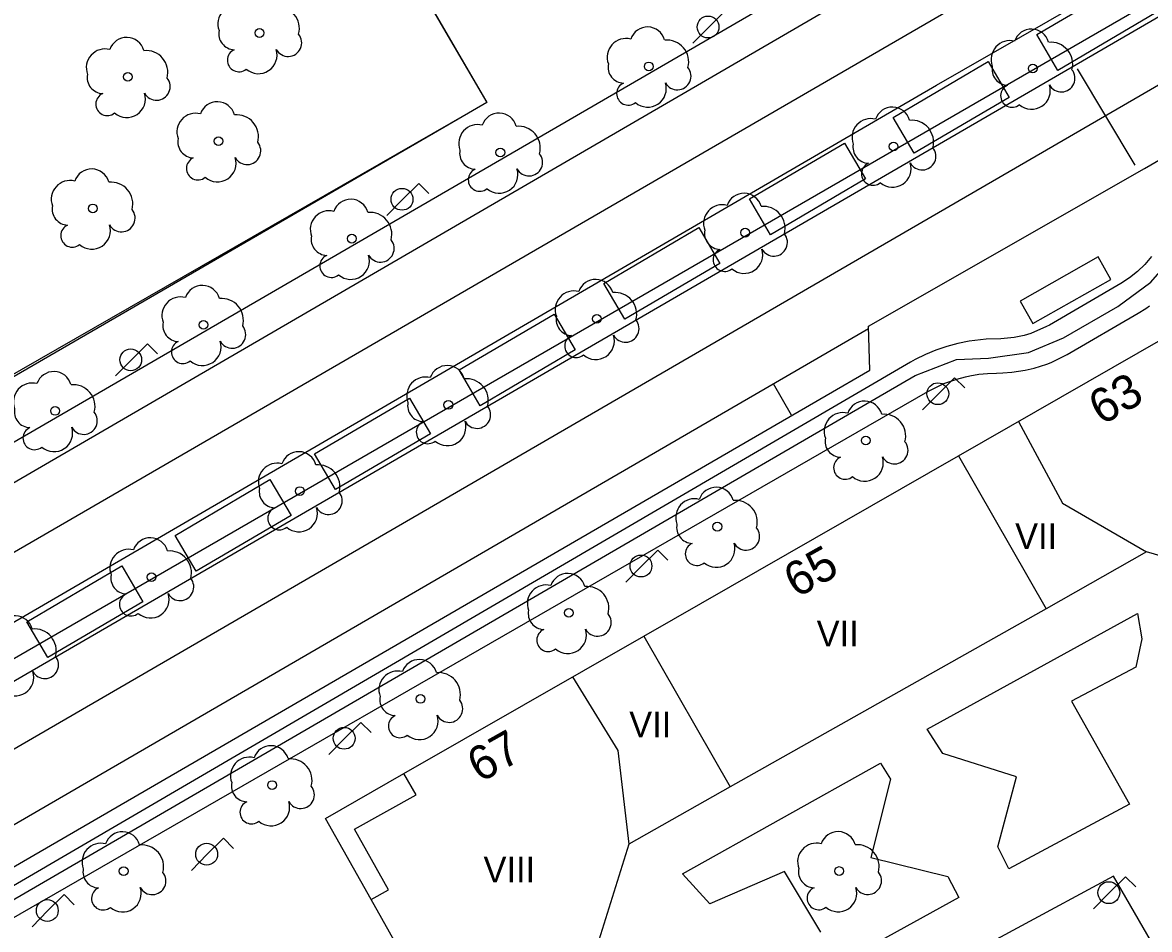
# Model space of a CAD drawing. Extents: x 282771 to 285132, y 4823109 to 4825496.
# Drawn here: x 283766.5 to 283832.3, y 4823743.4 to 4823796.3 of the extents above; entities that cross this region are included whole.
import ezdxf

# ---------------------------------------------------------------- set-up
doc = ezdxf.new("R2010")
doc.units = 0
for name, color, linetype in [('ACERA-BORDILLO', 7, 'Continuous'), ('ACERA-INTERIOR', 7, 'Continuous'), ('APARCAMIENTO', 7, 'Continuous'), ('ARBOL', 7, 'Continuous'), ('BORDILLO', 7, 'Continuous'), ('CALLE-EJE', 7, 'Continuous'), ('CARRIL-BICI-AREA', 7, 'Continuous'), ('CARRIL-BICI-EJE', 7, 'Continuous'), ('EDIFICIO', 7, 'Continuous'), ('FAROLA', 7, 'Continuous'), ('MARQUESINA-BUS', 7, 'Continuous'), ('MEDIANERA', 7, 'Continuous'), ('NUM-PORTAL', 7, 'Continuous'), ('PARQUE-JARDIN-AREA', 7, 'Continuous'), ('SENAL-VIARIA', 7, 'Continuous'), ('TXT-ALTURA-EDIFICIO', 7, 'Continuous'), ('ZONA-VERDE', 7, 'Continuous')]:
    doc.layers.add(name, color=color, linetype=linetype)

msp = doc.modelspace()

# ---------------------------------------------------------------- linework, layer by layer
at = {"layer": 'ACERA-BORDILLO'}
for points in [[(283686.965, 4823723.606), (283698.624, 4823730.373), (283698.444, 4823732.697), (283821.968, 4823804.368)], [(283708.328, 4823713.648), (283815.96, 4823776.062), (283815.877, 4823778.645), (283831.988, 4823787.83), (283834.54, 4823789.311)]]:
    msp.add_lwpolyline(points, dxfattribs=at)
at = {"layer": 'ACERA-INTERIOR'}
for points in [[(283786.872, 4823745.187), (283784.202, 4823749.927), (283788.772, 4823752.547)], [(283844.381, 4823721.987), (283830.181, 4823746.557), (283807.691, 4823734.427), (283822.111, 4823709.407), (283844.381, 4823721.987)]]:
    msp.add_lwpolyline(points, dxfattribs=at)
at = {"layer": 'APARCAMIENTO'}
for points in [[(283822.998, 4823802.633), (283760.545, 4823766.338), (283759.489, 4823768.01)], [(283811.392, 4823773.448), (283810.336, 4823775.267)]]:
    msp.add_lwpolyline(points, dxfattribs=at)
at = {"layer": 'ARBOL'}
for centre in [(283780.343, 4823795.741), (283803.06, 4823793.793), (283825.466, 4823793.668), (283772.668, 4823793.183), (283777.955, 4823789.431), (283794.399, 4823788.768), (283817.349, 4823789.118), (283770.622, 4823785.509), (283808.688, 4823784.093), (283785.739, 4823783.743), (283800.028, 4823779.068), (283777.078, 4823778.718), (283768.417, 4823773.693), (283791.367, 4823774.043), (283815.723, 4823771.968), (283782.706, 4823769.018), (283807.063, 4823766.943), (283774.046, 4823763.993), (283798.402, 4823761.918), (283789.741, 4823756.893), (283781.081, 4823751.868), (283772.42, 4823746.843), (283814.175, 4823746.853)]:
    msp.add_circle(centre, 0.255, dxfattribs=at)
for centre, radius, start, end in [((283779.013, 4823796.271), 1.097, 75.4318, 200.55608), ((283781.403, 4823796.001), 1.272, 345.03273, 95.79925), ((283778.903, 4823795.701), 0.935, 168.59898, 268.13236), ((283782.013, 4823795.171), 0.797, 208.96246, 38.99103), ((283802.99, 4823795.053), 1.038, 15.64228, 161.38435), ((283825.396, 4823794.928), 1.038, 15.64228, 161.38435), ((283772.598, 4823794.443), 1.038, 15.64228, 161.38435), ((283801.73, 4823794.323), 1.097, 75.4318, 200.55608), ((283804.12, 4823794.053), 1.272, 345.03273, 95.79925), ((283824.136, 4823794.198), 1.097, 75.4318, 200.55608), ((283826.526, 4823793.928), 1.272, 345.03273, 95.79925), ((283771.338, 4823793.713), 1.097, 75.4318, 200.55608), ((283773.728, 4823793.443), 1.272, 345.03273, 95.79925), ((283779.143, 4823794.151), 0.672, 113.73672, 309.4725), ((283780.283, 4823794.451), 1.086, 228.95447, 17.92796), ((283801.62, 4823793.753), 0.935, 168.59898, 268.13236), ((283804.73, 4823793.223), 0.797, 208.96246, 38.99103), ((283824.026, 4823793.628), 0.935, 168.59898, 268.13236), ((283827.136, 4823793.098), 0.797, 208.96246, 38.99103), ((283771.228, 4823793.143), 0.935, 168.59898, 268.13236), ((283774.338, 4823792.613), 0.797, 208.96246, 38.99103), ((283772.608, 4823791.893), 1.086, 228.95447, 17.92796), ((283801.86, 4823792.203), 0.672, 113.73672, 309.4725), ((283803, 4823792.503), 1.086, 228.95447, 17.92796), ((283824.266, 4823792.078), 0.672, 113.73672, 309.4725), ((283825.406, 4823792.378), 1.086, 228.95447, 17.92796), ((283771.468, 4823791.593), 0.672, 113.73672, 309.4725), ((283777.885, 4823790.691), 1.038, 15.64228, 161.38435), ((283776.625, 4823789.961), 1.097, 75.4318, 200.55608), ((283779.015, 4823789.691), 1.272, 345.03273, 95.79925), ((283794.329, 4823790.028), 1.038, 15.64228, 161.38435), ((283817.279, 4823790.378), 1.038, 15.64228, 161.38435), ((283793.07, 4823789.298), 1.097, 75.4318, 200.55608), ((283795.459, 4823789.028), 1.272, 345.03273, 95.79925), ((283816.019, 4823789.648), 1.097, 75.4318, 200.55608), ((283818.409, 4823789.378), 1.272, 345.03273, 95.79925), ((283776.515, 4823789.391), 0.935, 168.59898, 268.13236), ((283779.625, 4823788.861), 0.797, 208.96246, 38.99103), ((283815.909, 4823789.078), 0.935, 168.59898, 268.13236), ((283819.019, 4823788.548), 0.797, 208.96246, 38.99103), ((283776.755, 4823787.841), 0.672, 113.73672, 309.4725), ((283777.895, 4823788.141), 1.086, 228.95447, 17.92796), ((283792.96, 4823788.728), 0.935, 168.59898, 268.13236), ((283796.069, 4823788.198), 0.797, 208.96246, 38.99103), ((283770.552, 4823786.769), 1.038, 15.64228, 161.38435), ((283793.2, 4823787.178), 0.672, 113.73672, 309.4725), ((283794.339, 4823787.478), 1.086, 228.95447, 17.92796), ((283816.149, 4823787.528), 0.672, 113.73672, 309.4725), ((283817.289, 4823787.828), 1.086, 228.95447, 17.92796), ((283769.292, 4823786.039), 1.097, 75.4318, 200.55608), ((283771.682, 4823785.769), 1.272, 345.03273, 95.79925), ((283808.618, 4823785.353), 1.038, 15.64228, 161.38435), ((283769.182, 4823785.469), 0.935, 168.59898, 268.13236), ((283785.669, 4823785.003), 1.038, 15.64228, 161.38435), ((283807.358, 4823784.623), 1.097, 75.4318, 200.55608), ((283772.292, 4823784.939), 0.797, 208.96246, 38.99103), ((283784.409, 4823784.273), 1.097, 75.4318, 200.55608), ((283786.799, 4823784.003), 1.272, 345.03273, 95.79925), ((283809.748, 4823784.353), 1.272, 345.03273, 95.79925), ((283769.422, 4823783.919), 0.672, 113.73672, 309.4725), ((283770.562, 4823784.219), 1.086, 228.95447, 17.92796), ((283784.299, 4823783.703), 0.935, 168.59898, 268.13236), ((283807.248, 4823784.053), 0.935, 168.59898, 268.13236), ((283810.358, 4823783.523), 0.797, 208.96246, 38.99103), ((283787.409, 4823783.173), 0.797, 208.96246, 38.99103), ((283807.488, 4823782.503), 0.672, 113.73672, 309.4725), ((283808.628, 4823782.803), 1.086, 228.95447, 17.92796), ((283784.539, 4823782.153), 0.672, 113.73672, 309.4725), ((283785.679, 4823782.453), 1.086, 228.95447, 17.92796), ((283799.958, 4823780.328), 1.038, 15.64228, 161.38435), ((283777.008, 4823779.978), 1.038, 15.64228, 161.38435), ((283798.698, 4823779.598), 1.097, 75.4318, 200.55608), ((283801.088, 4823779.328), 1.272, 345.03273, 95.79925), ((283775.748, 4823779.248), 1.097, 75.4318, 200.55608), ((283778.138, 4823778.978), 1.272, 345.03273, 95.79925), ((283798.588, 4823779.028), 0.935, 168.59898, 268.13236), ((283775.638, 4823778.678), 0.935, 168.59898, 268.13236), ((283778.748, 4823778.148), 0.797, 208.96246, 38.99103), ((283801.698, 4823778.498), 0.797, 208.96246, 38.99103), ((283777.018, 4823777.428), 1.086, 228.95447, 17.92796), ((283798.828, 4823777.478), 0.672, 113.73672, 309.4725), ((283799.968, 4823777.778), 1.086, 228.95447, 17.92796), ((283775.878, 4823777.128), 0.672, 113.73672, 309.4725), ((283768.347, 4823774.953), 1.038, 15.64228, 161.38435), ((283791.297, 4823775.303), 1.038, 15.64228, 161.38435), ((283767.087, 4823774.223), 1.097, 75.4318, 200.55608), ((283769.477, 4823773.953), 1.272, 345.03273, 95.79925), ((283790.037, 4823774.573), 1.097, 75.4318, 200.55608), ((283792.427, 4823774.303), 1.272, 345.03273, 95.79925), ((283766.977, 4823773.653), 0.935, 168.59898, 268.13236), ((283789.927, 4823774.003), 0.935, 168.59898, 268.13236), ((283793.037, 4823773.473), 0.797, 208.96246, 38.99103), ((283815.653, 4823773.228), 1.038, 15.64228, 161.38435), ((283770.087, 4823773.123), 0.797, 208.96246, 38.99103), ((283814.393, 4823772.498), 1.097, 75.4318, 200.55608), ((283816.783, 4823772.228), 1.272, 345.03273, 95.79925), ((283767.217, 4823772.103), 0.672, 113.73672, 309.4725), ((283768.357, 4823772.403), 1.086, 228.95447, 17.92796), ((283790.167, 4823772.453), 0.672, 113.73672, 309.4725), ((283791.307, 4823772.753), 1.086, 228.95447, 17.92796), ((283814.283, 4823771.928), 0.935, 168.59898, 268.13236), ((283817.393, 4823771.398), 0.797, 208.96246, 38.99103), ((283782.636, 4823770.278), 1.038, 15.64228, 161.38435), ((283781.376, 4823769.548), 1.097, 75.4318, 200.55608), ((283783.766, 4823769.278), 1.272, 345.03273, 95.79925), ((283814.523, 4823770.378), 0.672, 113.73672, 309.4725), ((283815.663, 4823770.678), 1.086, 228.95447, 17.92796), ((283806.993, 4823768.203), 1.038, 15.64228, 161.38435), ((283781.266, 4823768.978), 0.935, 168.59898, 268.13236), ((283784.376, 4823768.448), 0.797, 208.96246, 38.99103), ((283805.733, 4823767.473), 1.097, 75.4318, 200.55608), ((283781.506, 4823767.428), 0.672, 113.73672, 309.4725), ((283782.646, 4823767.728), 1.086, 228.95447, 17.92796), ((283808.123, 4823767.203), 1.272, 345.03273, 95.79925), ((283805.623, 4823766.903), 0.935, 168.59898, 268.13236), ((283808.733, 4823766.373), 0.797, 208.96246, 38.99103), ((283773.976, 4823765.253), 1.038, 15.64228, 161.38435), ((283805.863, 4823765.353), 0.672, 113.73672, 309.4725), ((283807.003, 4823765.653), 1.086, 228.95447, 17.92796), ((283772.716, 4823764.523), 1.097, 75.4318, 200.55608), ((283775.106, 4823764.253), 1.272, 345.03273, 95.79925), ((283772.606, 4823763.953), 0.935, 168.59898, 268.13236), ((283798.332, 4823763.178), 1.038, 15.64228, 161.38435), ((283775.716, 4823763.423), 0.797, 208.96246, 38.99103), ((283797.072, 4823762.448), 1.097, 75.4318, 200.55608), ((283799.462, 4823762.178), 1.272, 345.03273, 95.79925), ((283772.846, 4823762.403), 0.672, 113.73672, 309.4725), ((283773.986, 4823762.703), 1.086, 228.95447, 17.92796), ((283796.962, 4823761.878), 0.935, 168.59898, 268.13236), ((283766.083, 4823760.705), 1.038, 15.64228, 161.38435), ((283800.072, 4823761.348), 0.797, 208.96246, 38.99103), ((283767.213, 4823759.705), 1.272, 345.03273, 95.79925), ((283797.202, 4823760.328), 0.672, 113.73672, 309.4725), ((283798.342, 4823760.628), 1.086, 228.95447, 17.92796), ((283767.823, 4823758.875), 0.797, 208.96246, 38.99103), ((283789.671, 4823758.153), 1.038, 15.64228, 161.38435), ((283766.093, 4823758.155), 1.086, 228.95447, 17.92796), ((283788.411, 4823757.423), 1.097, 75.4318, 200.55608), ((283790.801, 4823757.153), 1.272, 345.03273, 95.79925), ((283788.301, 4823756.853), 0.935, 168.59898, 268.13236), ((283791.411, 4823756.323), 0.797, 208.96246, 38.99103), ((283788.541, 4823755.303), 0.672, 113.73672, 309.4725), ((283789.681, 4823755.603), 1.086, 228.95447, 17.92796), ((283781.011, 4823753.128), 1.038, 15.64228, 161.38435), ((283779.751, 4823752.398), 1.097, 75.4318, 200.55608), ((283782.141, 4823752.128), 1.272, 345.03273, 95.79925), ((283779.641, 4823751.828), 0.935, 168.59898, 268.13236), ((283782.751, 4823751.298), 0.797, 208.96246, 38.99103), ((283779.881, 4823750.278), 0.672, 113.73672, 309.4725), ((283781.021, 4823750.578), 1.086, 228.95447, 17.92796), ((283772.35, 4823748.103), 1.038, 15.64228, 161.38435), ((283814.105, 4823748.113), 1.038, 15.64228, 161.38435), ((283771.09, 4823747.373), 1.097, 75.4318, 200.55608), ((283773.48, 4823747.103), 1.272, 345.03273, 95.79925), ((283812.845, 4823747.383), 1.097, 75.4318, 200.55608), ((283815.235, 4823747.113), 1.272, 345.03273, 95.79925), ((283770.98, 4823746.803), 0.935, 168.59898, 268.13236), ((283812.735, 4823746.813), 0.935, 168.59898, 268.13236), ((283774.09, 4823746.273), 0.797, 208.96246, 38.99103), ((283815.845, 4823746.283), 0.797, 208.96246, 38.99103), ((283771.22, 4823745.253), 0.672, 113.73672, 309.4725), ((283772.36, 4823745.553), 1.086, 228.95447, 17.92796), ((283812.975, 4823745.263), 0.672, 113.73672, 309.4725), ((283814.115, 4823745.563), 1.086, 228.95447, 17.92796)]:
    msp.add_arc(centre, radius, start, end, dxfattribs=at)
at = {"layer": 'BORDILLO'}
for points in [[(283691.749, 4823718.19), (283819.843, 4823792.692), (283831.283, 4823799.266)], [(283834.164, 4823797.465), (283693.206, 4823715.678), (283692.966, 4823715.567), (283692.693, 4823715.498), (283692.4, 4823715.484), (283692.105, 4823715.531), (283691.825, 4823715.637), (283691.578, 4823715.794), (283691.375, 4823715.989), (283691.222, 4823716.205), (283691.11, 4823716.446), (283691.042, 4823716.719), (283691.028, 4823717.011), (283691.075, 4823717.307), (283691.181, 4823717.586), (283691.338, 4823717.834), (283691.533, 4823718.036), (283691.749, 4823718.19)]]:
    msp.add_lwpolyline(points, dxfattribs=at)
at = {"layer": 'CALLE-EJE'}
msp.add_lwpolyline([(283685.293, 4823712.647), (283840.771, 4823802.436)], dxfattribs=at)
at = {"layer": 'CARRIL-BICI-AREA'}
for points in [[(283832.393, 4823782.701), (283832.006, 4823782.243), (283831.579, 4823781.821), (283831.11, 4823781.45), (283830.613, 4823781.124), (283826.444, 4823778.705), (283826.27, 4823778.611), (283825.359, 4823778.212), (283824.976, 4823778.096), (283824.388, 4823777.974), (283823.597, 4823777.899), (283822.741, 4823777.875), (283822.411, 4823777.844), (283821.752, 4823777.759), (283821.098, 4823777.631), (283820.453, 4823777.459), (283819.822, 4823777.245), (283819.208, 4823776.99), (283818.616, 4823776.697), (283818.326, 4823776.541), (283706.898, 4823711.519)], [(283687.107, 4823698.758), (283819.354, 4823774.823), (283819.812, 4823775.069), (283820.289, 4823775.286), (283821.032, 4823775.55), (283821.541, 4823775.687), (283821.797, 4823775.748), (283822.316, 4823775.834), (283822.837, 4823775.886), (283823.357, 4823775.905), (283823.73, 4823775.914), (283824.251, 4823775.949), (283825.03, 4823776.062), (283825.543, 4823776.182), (283826.293, 4823776.43), (283826.538, 4823776.523), (283827.244, 4823776.863), (283827.473, 4823776.987), (283831.626, 4823779.397), (283832.068, 4823779.672), (283832.28, 4823779.825)]]:
    msp.add_lwpolyline(points, dxfattribs=at)
at = {"layer": 'CARRIL-BICI-EJE'}
msp.add_lwpolyline([(283510.08, 4823597.633), (283706.223, 4823710.47), (283818.613, 4823775.756), (283821.019, 4823776.694), (283822.894, 4823776.775), (283825.218, 4823777.102), (283827.257, 4823777.958), (283830.437, 4823779.794), (283832.354, 4823781.206), (283833.565, 4823782.581), (283834.753, 4823784.562), (283836.081, 4823785.728), (283840.159, 4823788.035), (283860.751, 4823800.066)], dxfattribs=at)
at = {"layer": 'EDIFICIO'}
for points in [[(283786.872, 4823745.187), (283787.872, 4823745.747), (283785.882, 4823749.287), (283789.482, 4823751.307), (283788.772, 4823752.547), (283802.781, 4823760.557), (283821.141, 4823771.077), (283834.681, 4823778.837), (283835.391, 4823777.577), (283839.011, 4823779.617), (283841.031, 4823776.017), (283842.321, 4823776.737), (283850.911, 4823761.347), (283861.741, 4823741.987), (283869.831, 4823727.557)], [(283870.931, 4823723.667), (283867.291, 4823721.627), (283868.011, 4823720.337), (283852.961, 4823711.937), (283848.093, 4823720.613), (283855.141, 4823724.567), (283856.781, 4823730.677), (283853.091, 4823737.147), (283842.131, 4823756.437), (283837.971, 4823763.767), (283832.111, 4823765.467), (283826.251, 4823762.157), (283807.821, 4823751.767), (283801.901, 4823748.427), (283799.961, 4823742.197), (283804.031, 4823735.347), (283795.332, 4823730.127), (283786.872, 4823745.187)]]:
    msp.add_lwpolyline(points, dxfattribs=at)
at = {"layer": 'FAROLA'}
for p, q in [((283807.503, 4823797.019), (283806.563, 4823796.089)), ((283806.563, 4823796.089), (283805.633, 4823795.149)), ((283789.643, 4823786.969), (283788.703, 4823786.039)), ((283790.233, 4823786.379), (283789.643, 4823786.969)), ((283788.703, 4823786.039), (283787.773, 4823785.099)), ((283773.813, 4823777.606), (283772.873, 4823776.676)), ((283774.403, 4823777.016), (283773.813, 4823777.606)), ((283772.873, 4823776.676), (283771.943, 4823775.736)), ((283820.908, 4823775.627), (283819.968, 4823774.697)), ((283821.498, 4823775.037), (283820.908, 4823775.627)), ((283819.968, 4823774.697), (283819.038, 4823773.757)), ((283803.587, 4823765.577), (283802.647, 4823764.647)), ((283804.177, 4823764.987), (283803.587, 4823765.577)), ((283802.647, 4823764.647), (283801.717, 4823763.707)), ((283786.265, 4823755.527), (283785.325, 4823754.597)), ((283786.855, 4823754.937), (283786.265, 4823755.527)), ((283785.325, 4823754.597), (283784.395, 4823753.657)), ((283778.243, 4823748.763), (283777.303, 4823747.833)), ((283778.833, 4823748.173), (283778.243, 4823748.763)), ((283777.303, 4823747.833), (283776.373, 4823746.893)), ((283830.887, 4823746.522), (283829.947, 4823745.592)), ((283831.477, 4823745.932), (283830.887, 4823746.522)), ((283829.947, 4823745.592), (283829.017, 4823744.652)), ((283768.944, 4823745.477), (283768.004, 4823744.547)), ((283769.534, 4823744.887), (283768.944, 4823745.477)), ((283768.004, 4823744.547), (283767.074, 4823743.607))]:
    msp.add_line(p, q, dxfattribs=at)
for centre in [(283806.523, 4823796.089), (283788.663, 4823786.039), (283772.833, 4823776.676), (283819.928, 4823774.697), (283802.607, 4823764.647), (283785.285, 4823754.597), (283777.263, 4823747.833), (283829.907, 4823745.592), (283767.964, 4823744.547)]:
    msp.add_circle(centre, 0.637, dxfattribs=at)
at = {"layer": 'MARQUESINA-BUS'}
msp.add_lwpolyline([(283825.481, 4823778.795), (283830.025, 4823781.366), (283829.286, 4823782.673), (283824.742, 4823780.102), (283825.481, 4823778.795)], dxfattribs=at)
at = {"layer": 'MEDIANERA'}
for points in [[(283824.631, 4823773.077), (283827.211, 4823768.307), (283832.111, 4823765.467)], [(283821.141, 4823771.077), (283826.251, 4823762.157)], [(283802.781, 4823760.557), (283807.821, 4823751.767)], [(283798.611, 4823758.177), (283801.261, 4823753.877), (283801.901, 4823748.427)]]:
    msp.add_lwpolyline(points, dxfattribs=at)
at = {"layer": 'PARQUE-JARDIN-AREA'}
msp.add_lwpolyline([(283728.041, 4823827.883), (283730.641, 4823830.661), (283732.016, 4823831.84), (283745.833, 4823816.067), (283838.477, 4823896.142), (283853.871, 4823877.753), (283821.415, 4823849.784), (283818.024, 4823845.784), (283817.33, 4823844.721), (283816.785, 4823843.548), (283816.303, 4823842.103), (283815.882, 4823840.206), (283815.542, 4823838.304), (283810.304, 4823834.874), (283778.974, 4823816.824), (283793.604, 4823791.683), (283763.272, 4823774.291), (283760.222, 4823772.248)], close=True, dxfattribs=at)
at = {"layer": 'SENAL-VIARIA'}
msp.add_line((283815.882, 4823778.485), (283707.273, 4823715.467), dxfattribs=at)
for points in [[(283830.653, 4823802.914), (283700.335, 4823727.388)], [(283703.559, 4823717.746), (283834.516, 4823793.702)], [(283831.447, 4823788.022), (283828.085, 4823793.645)]]:
    msp.add_lwpolyline(points, dxfattribs=at)
at = {"layer": 'ZONA-VERDE'}
for p, q in [((283778.974, 4823816.824), (283791.354, 4823795.543)), ((283825.703, 4823795.645), (283832.771, 4823799.807)), ((283834.001, 4823797.719), (283826.933, 4823793.557)), ((283791.354, 4823795.543), (283793.604, 4823791.683)), ((283826.933, 4823793.557), (283825.703, 4823795.645)), ((283817.329, 4823790.816), (283822.87, 4823794.07)), ((283822.87, 4823794.07), (283824.097, 4823791.98)), ((283793.604, 4823791.683), (283790.494, 4823789.873)), ((283824.097, 4823791.98), (283818.557, 4823788.726)), ((283818.557, 4823788.726), (283817.329, 4823790.816)), ((283790.494, 4823789.873), (283763.882, 4823774.455)), ((283808.947, 4823786.059), (283814.487, 4823789.313)), ((283814.487, 4823789.313), (283815.715, 4823787.223)), ((283815.715, 4823787.223), (283810.174, 4823783.969)), ((283810.174, 4823783.969), (283808.947, 4823786.059)), ((283800.443, 4823781.13), (283805.984, 4823784.384)), ((283805.984, 4823784.384), (283807.211, 4823782.294)), ((283807.211, 4823782.294), (283801.671, 4823779.04)), ((283801.671, 4823779.04), (283800.443, 4823781.13)), ((283791.998, 4823776.089), (283797.538, 4823779.344)), ((283797.538, 4823779.344), (283798.766, 4823777.254)), ((283798.766, 4823777.254), (283793.225, 4823774)), ((283793.225, 4823774), (283791.998, 4823776.089)), ((283783.555, 4823771.192), (283789.095, 4823774.446)), ((283789.095, 4823774.446), (283790.323, 4823772.356)), ((283790.323, 4823772.356), (283784.782, 4823769.102)), ((283784.782, 4823769.102), (283783.555, 4823771.192)), ((283775.419, 4823766.434), (283780.959, 4823769.689)), ((283780.959, 4823769.689), (283782.187, 4823767.599)), ((283782.187, 4823767.599), (283776.646, 4823764.345)), ((283776.646, 4823764.345), (283775.419, 4823766.434)), ((283766.767, 4823761.394), (283772.307, 4823764.649)), ((283772.307, 4823764.649), (283773.535, 4823762.559)), ((283773.535, 4823762.559), (283767.994, 4823759.304)), ((283767.994, 4823759.304), (283766.767, 4823761.394)), ((283819.303, 4823755.123), (283831.574, 4823761.874)), ((283831.574, 4823761.874), (283831.833, 4823760.394)), ((283831.833, 4823760.394), (283831.483, 4823758.744)), ((283831.483, 4823758.744), (283827.733, 4823756.763)), ((283827.733, 4823756.763), (283831.113, 4823750.753)), ((283820.223, 4823753.703), (283819.303, 4823755.123)), ((283824.523, 4823752.343), (283820.223, 4823753.703)), ((283805.033, 4823746.683), (283816.593, 4823753.153)), ((283816.593, 4823753.153), (283817.163, 4823752.203)), ((283817.163, 4823752.203), (283816.023, 4823747.633)), ((283823.423, 4823748.263), (283824.523, 4823752.343)), ((283831.113, 4823750.753), (283824.073, 4823746.973)), ((283824.073, 4823746.973), (283823.423, 4823748.263)), ((283816.023, 4823747.633), (283820.513, 4823746.533)), ((283806.633, 4823744.933), (283805.033, 4823746.683)), ((283810.983, 4823746.823), (283806.633, 4823744.933)), ((283813.103, 4823743.283), (283810.983, 4823746.823)), ((283820.513, 4823746.533), (283821.163, 4823745.303)), ((283821.163, 4823745.303), (283815.863, 4823742.393))]:
    msp.add_line(p, q, dxfattribs=at)

# ---------------------------------------------------------------- texts
at = {"layer": 'NUM-PORTAL'}
for s, p in [('63', (283829.478, 4823772.825)), ('65', (283811.687, 4823762.749)), ('67', (283793.213, 4823751.973))]:
    msp.add_text(s, height=2, rotation=29.30004, dxfattribs=at).set_placement(p)
at = {"layer": 'TXT-ALTURA-EDIFICIO'}
for s, p in [('VII', (283824.441, 4823765.637)), ('VII', (283812.861, 4823759.957)), ('VII', (283801.921, 4823754.657)), ('VIII', (283793.421, 4823746.187))]:
    msp.add_text(s, height=1.5, rotation=0.00004, dxfattribs=at).set_placement(p)

doc.saveas('drawing.dxf')
